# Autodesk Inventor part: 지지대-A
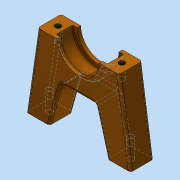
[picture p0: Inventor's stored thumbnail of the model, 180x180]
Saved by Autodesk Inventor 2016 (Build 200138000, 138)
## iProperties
Created: 2018-01
Part Number: 지지대-A
Material: 알루미늄 6061
Document SubType Name: Modeling
Designer: mduedu
Density: 2.71 g/cm^3
Appearance: 주황색
Mass: 21.9456 g
Surface Area: 38.5771 cm^2
Volume: 8.09801 cm^3
Author: mduedu
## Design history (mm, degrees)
sketch "스케치1"
  geometry: L1 (-22.5, 0)-(22.5, 0); L2 (22.5, 0)-(17.5, 34); L3 (17.5, 34)-(-17.5, 34); L4 (-17.5, 34)-(-22.5, 0); 3 further points
  constraints: 8 end point, 2 midpoint, 1 coincident, 1 horizontal, 1 parallel, 1 vertical alignment
  dimensions: "d0" = 45 distance of L1.start L1.end; "d3" = 35 distance of L2.end L3.end; "d4" = 34 vertical distance of L1.end L2.end
extrude "돌출1" new body sketch "스케치1" stored distance "d5" = 10; taper "d6" = 0 deg
sketch "스케치2"
  geometry: L1 (-12.5, 0)-(12.5, 0); L2 (12.5, 0)-(7.5, 18); L3 (7.5, 18)-(-7.5, 18); L4 (-7.5, 18)-(-12.5, 0); L5 (-22.5, 0)-(22.5, 0) reference; 4 further points
  constraints: 8 end point, 4 midpoint, 1 horizontal, 1 parallel, 1 vertical alignment
  dimensions: "d7" = 10 distance of L1.start L5.start; "d8" = 10 distance of L1.end L5.end (derived); "d9" = 15 distance of L2.end L3.end; "d10" = 18 distance between parallel lines of L1 L3
extrude "돌출2" cut sketch "스케치2" stored distance "d11" = 10; taper "d12" = 0 deg
sketch "스케치3"
  geometry: L1 (-17.5, 34)-(17.5, 34) reference; C1 r 11 at (0, 34); C2 r 9 at (0, 34); 1 further point
  constraints: 2 centre point, 1 coincident, 1 midpoint
  dimensions: "d13" = 22 diameter of C1; "d16" = 18 diameter of C2
extrude "돌출3" cut sketch "스케치3" stored distance "d14" = 7; taper "d15" = 0 deg
extrude "돌출4" cut sketch "스케치3" stored distance "d17" = 7; taper "d18" = 0 deg
fillet "모깎기1" dims "d19" = 0.3
fillet "모깎기2" dims "d20" = 1
fillet "모깎기3" dims "d21" = 1
fillet "모깎기4" dims "d22" = 1
sketch "스케치4"
  geometry: 2 further points
  constraints: 2 other
hole "구멍1" sketch "스케치4" at (-22.771, -3.5), (4.771, -3.5) diameter "d23" = 2.459; stored, may be unused: countersink angle "d27" = 90 deg, drill point angle "d29" = 120 deg; dims "d24" = 4.5, "d25" = 4, "d26" = 2, "d28" = 6
sketch "스케치5"
  geometry: 4 further points
  constraints: 4 other
hole "구멍2" sketch "스케치5" at (40, 4), (5, -27), (40, -27), (5, 4) diameter "d30" = 2.459; stored, may be unused: countersink angle "d34" = 90 deg, drill point angle "d36" = 120 deg; dims "d31" = 6.9, "d32" = 4, "d33" = 2, "d35" = 8.4
node "솔리드1"
